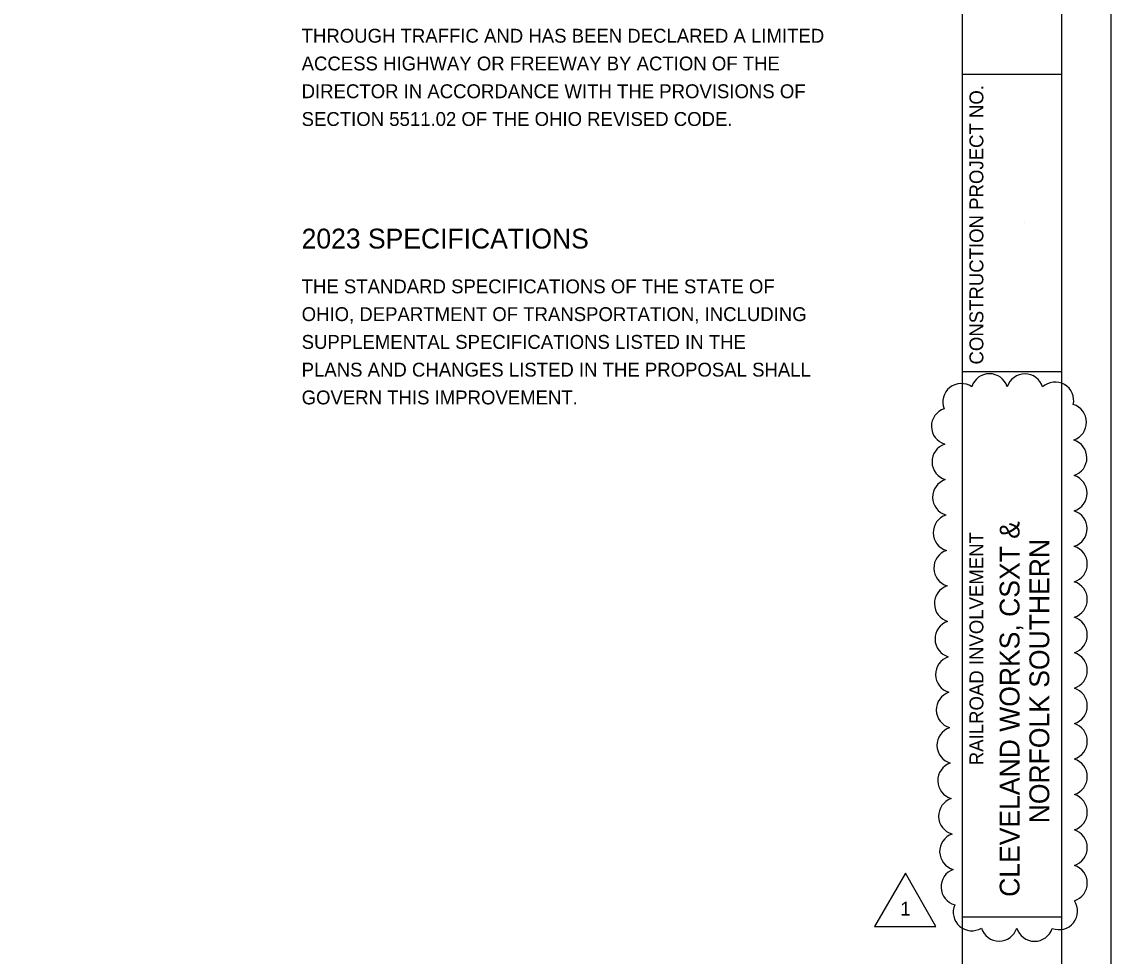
# Model space of a CAD drawing. Extents: x 0 to 96.2, y -27.5 to 31.3.
# Drawn here: x 64.23 to 75.22, y 5.49 to 14.92 of the extents above; entities that cross this region are included whole.
import ezdxf

# ---------------------------------------------------------------- set-up
doc = ezdxf.new("R2010")
doc.units = 0
for name, color, linetype in [('DIM', 7, 'Continuous'), ('TB1', 7, 'Continuous'), ('TB_SUPER_50x1', 7, 'Continuous'), ('TB_SUPER_50x1_GRID', 7, 'Continuous'), ('text', 7, 'Continuous')]:
    doc.layers.add(name, color=color, linetype=linetype)

msp = doc.modelspace()

# ---------------------------------------------------------------- linework, layer by layer
at = {"layer": 'DIM'}
for p, q in [((73.723, 0.387), (73.723, 21.387)), ((73.723, 14.387), (74.723, 14.387)), ((73.723, 11.387), (74.723, 11.387)), ((73.723, 5.887), (74.723, 5.887))]:
    msp.add_line(p, q, dxfattribs=at)
msp.add_lwpolyline([(43.223, 21.387), (74.723, 21.387), (74.723, 0.387), (43.223, 0.387)], close=True, dxfattribs=at)
at = {"layer": 'TB1'}
for p, q in [((74.348, 12.887), (74.348, 12.887)), ((74.348, 8.653), (74.348, 8.653))]:
    msp.add_line(p, q, dxfattribs=at)
at = {"layer": 'TB_SUPER_50x1_GRID'}
msp.add_lwpolyline([(72.836, 5.792), (73.455, 5.792), (73.146, 6.328)], close=True, dxfattribs=at)
for centre, start, end in [((73.995, 11.179), 17.5, 162.5), ((74.352, 11.178), 17.082, 162.082), ((73.711, 11.08), 55.9336, 200.9336), ((74.658, 11.095), 347.645, 132.645), ((73.596, 10.836), 108.4757, 253.4757), ((74.787, 10.876), 288.2749, 73.2749), ((74.791, 10.518), 287.8954, 72.8954), ((73.602, 10.478), 108.4757, 253.4757), ((74.793, 10.161), 287.7447, 72.7447), ((73.608, 10.121), 108.4757, 253.4757), ((73.614, 9.763), 108.4757, 253.4757), ((74.794, 9.804), 287.6572, 72.6572), ((73.62, 9.406), 108.4757, 253.4757), ((74.795, 9.446), 287.5983, 72.5983), ((74.795, 9.089), 287.555, 72.555), ((73.626, 9.048), 108.4757, 253.4757), ((74.795, 8.731), 287.5215, 72.5215), ((73.632, 8.691), 108.4757, 253.4757), ((73.638, 8.333), 108.5082, 253.5082), ((74.795, 8.374), 287.501, 72.501), ((73.645, 7.976), 108.5858, 253.5858), ((74.795, 8.016), 287.5, 72.5), ((74.795, 7.659), 287.5, 72.5), ((73.652, 7.619), 108.6851, 253.6851), ((74.795, 7.301), 287.5, 72.5), ((73.66, 7.262), 108.8188, 253.8188), ((73.668, 6.904), 109.0127, 254.0127), ((74.795, 6.944), 287.5, 72.5), ((73.679, 6.547), 109.3328, 254.3328), ((74.795, 6.586), 287.5, 72.5), ((74.795, 6.229), 287.5, 72.5), ((73.693, 6.191), 110.0407, 255.0407), ((74.696, 5.946), 248.847, 33.847), ((73.816, 5.935), 156.417, 301.417), ((74.092, 5.831), 197.5, 342.5), ((74.45, 5.829), 196.8869, 341.8869)]:
    msp.add_arc(centre, 0.187, start, end, dxfattribs=at)
at = {"layer": 'text'}
msp.add_lwpolyline([(41.223, -0.113), (75.223, -0.113), (75.223, 21.887), (41.223, 21.887)], close=True, dxfattribs=at)

# ---------------------------------------------------------------- texts
at = {"layer": 'TB1'}
for s, height, p in [('THROUGH TRAFFIC AND HAS BEEN DECLARED A LIMITED', 0.14, (67.053, 14.705)), ('ACCESS HIGHWAY OR FREEWAY BY ACTION OF THE', 0.14, (67.053, 14.425)), ('DIRECTOR IN ACCORDANCE WITH THE PROVISIONS OF', 0.14, (67.053, 14.145)), ('SECTION 5511.02 OF THE OHIO REVISED CODE.', 0.14, (67.053, 13.865)), ('2023 SPECIFICATIONS', 0.2, (67.053, 12.629)), ('THE STANDARD SPECIFICATIONS OF THE STATE OF', 0.14, (67.053, 12.177)), ('OHIO, DEPARTMENT OF TRANSPORTATION, INCLUDING', 0.14, (67.053, 11.897)), ('SUPPLEMENTAL SPECIFICATIONS LISTED IN THE', 0.14, (67.053, 11.617)), ('PLANS AND CHANGES LISTED IN THE PROPOSAL SHALL', 0.14, (67.053, 11.337)), ('GOVERN THIS IMPROVEMENT.', 0.14, (67.053, 11.057))]:
    msp.add_text(s, height=height, dxfattribs=at).set_placement(p)
for s, p in [('CONSTRUCTION PROJECT NO.', (73.933, 11.459)), ('RAILROAD INVOLVEMENT', (73.933, 7.418))]:
    msp.add_text(s, height=0.14, rotation=90, dxfattribs=at).set_placement(p)
at = {"layer": 'TB_SUPER_50x1'}
for s, p in [('CLEVELAND WORKS, CSXT &', (74.298, 6.09)), ('NORFOLK SOUTHERN', (74.598, 6.832))]:
    msp.add_text(s, height=0.2, rotation=90, dxfattribs=at).set_placement(p)
at = {"layer": 'TB_SUPER_50x1_GRID'}
msp.add_text('1', height=0.14, dxfattribs=at).set_placement((73.095, 5.901))

doc.saveas('drawing.dxf')
